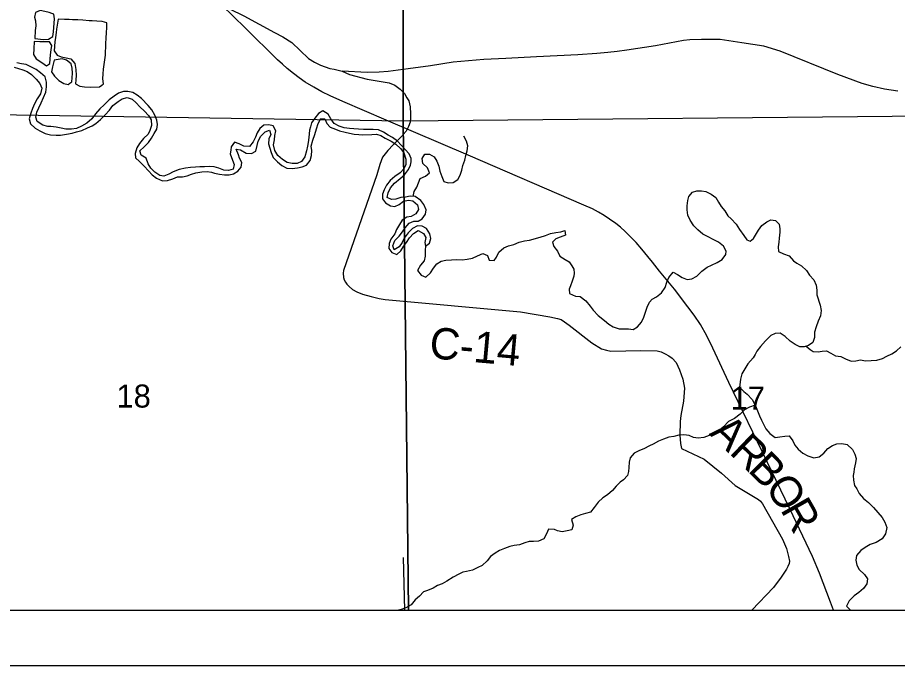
# Model space of a CAD drawing. Extents: x 0 to 34, y 0 to 22.
# Drawn here: x 6.566 to 8.162, y 14 to 15.175 of the extents above; entities that cross this region are included whole.
import ezdxf

# ---------------------------------------------------------------- set-up
doc = ezdxf.new("R2010")
doc.units = 0
for name, color, linetype in [('Default', 7, 'Continuous'), ('SH_Cut_Line', 7, 'Continuous'), ('SH_Data', 7, 'Continuous')]:
    doc.layers.add(name, color=color, linetype=linetype)

msp = doc.modelspace()

# ---------------------------------------------------------------- linework, layer by layer
at = {"layer": 'Default'}
msp.add_line((7.2687, 14.1), (7.2659, 14.1955), dxfattribs=at)
for points in [[(6.2892, 14.1), (8.9, 14.1), (8.9, 17.02), (8.2009, 17.0196), (7.211, 17.0191), (7.2045, 17.0191), (6.9328, 17.0189), (6.927, 17.0189), (6.6903, 17.0144), (6.3876, 17.0173), (6.3215, 17.0189), (6.2871, 17.0188), (6.2922, 16.0152), (6.2959, 15.2705), (6.2926, 14.8972), (6.2889, 14.4906), (6.2892, 14.18)], [(6.2943, 15.9991), (7.265, 16.0012), (7.2656, 14.9873), (6.2908, 15.0024), (6.2933, 15.4392)], [(8.2726, 16.0048), (8.2795, 14.9973), (7.2656, 14.9873), (7.265, 16.0012)], [(6.2854, 14.1), (7.2754, 14.1), (7.2656, 14.9873), (6.2908, 15.0024), (6.2858, 14.4391)], [(7.2754, 14.1), (8.2792, 14.1), (8.2795, 14.9973), (7.2656, 14.9873)]]:
    msp.add_lwpolyline(points, close=True, dxfattribs=at)
for points in [[(6.5394, 15.5399), (6.5899, 15.4855), (6.6708, 15.4021), (6.6928, 15.3789), (6.7527, 15.3164), (6.7777, 15.2904), (6.7991, 15.2728), (6.8123, 15.2654), (6.8735, 15.2322), (6.9245, 15.2039), (6.9768, 15.1783), (7.032, 15.1484), (7.0474, 15.1405), (7.0639, 15.1301), (7.0941, 15.1014), (7.1046, 15.0944), (7.1157, 15.0892), (7.1244, 15.0858), (7.1323, 15.083), (7.1403, 15.0815), (7.1549, 15.078)], [(8.046, 14.1), (8.0406, 14.1147), (8.021, 14.1674), (8.0082, 14.1978), (7.9667, 14.2843), (7.9256, 14.3692), (7.8563, 14.5132), (7.827, 14.5753), (7.8163, 14.5979), (7.8047, 14.6184), (7.7934, 14.6353), (7.782, 14.6504), (7.7575, 14.6826), (7.7308, 14.7151), (7.7176, 14.7314), (7.7092, 14.7421), (7.6986, 14.7552), (7.688, 14.767), (7.6773, 14.7784), (7.6682, 14.7875), (7.6597, 14.7951), (7.6512, 14.802), (7.6401, 14.8099), (7.6304, 14.8161), (7.6199, 14.8226), (7.6089, 14.8284), (7.5935, 14.8349), (7.3834, 14.9256), (7.235, 14.9895), (7.1561, 15.0234), (7.1332, 15.0336), (7.1183, 15.0408), (7.1038, 15.049), (7.0881, 15.0585), (7.077, 15.0663), (7.0666, 15.0738), (7.0552, 15.0829), (7.0465, 15.0906), (7.0376, 15.0989), (6.9791, 15.1568), (6.9366, 15.1982)], [(6.6281, 15.183), (6.6234, 15.1845), (6.6154, 15.1867), (6.6074, 15.1881), (6.5984, 15.1846), (6.5966, 15.1762), (6.5986, 15.1697), (6.5991, 15.1603), (6.5981, 15.1519), (6.5972, 15.1373)], [(6.5972, 15.1373), (6.6131, 15.1358), (6.6222, 15.1363), (6.6302, 15.141), (6.6312, 15.1493), (6.6322, 15.1573), (6.6325, 15.1653), (6.6331, 15.1733), (6.6322, 15.1816), (6.6281, 15.183)], [(6.6398, 15.1723), (6.6368, 15.1543), (6.6361, 15.1483), (6.6347, 15.1395), (6.6337, 15.1315), (6.6324, 15.1148), (6.6379, 15.1069), (6.6455, 15.1043), (6.6543, 15.1026), (6.6626, 15.1004), (6.67, 15.0921), (6.6717, 15.0812), (6.6722, 15.0705), (6.6719, 15.0625), (6.6713, 15.0549), (6.6793, 15.0509), (6.6877, 15.0495), (6.6976, 15.0492), (6.7146, 15.0495), (6.7193, 15.053)], [(6.7193, 15.053), (6.7218, 15.0549), (6.7209, 15.064), (6.7215, 15.0731), (6.7221, 15.0819), (6.7235, 15.0902), (6.7256, 15.1074), (6.7259, 15.1131), (6.7261, 15.1218), (6.7264, 15.1286), (6.7267, 15.1378), (6.7273, 15.1484), (6.7279, 15.1568), (6.7281, 15.1659), (6.7194, 15.168), (6.7099, 15.169), (6.7015, 15.1697), (6.6958, 15.1692), (6.6848, 15.1706), (6.6753, 15.1712), (6.6658, 15.1715), (6.6597, 15.1718), (6.6514, 15.1716), (6.6398, 15.1723)], [(6.5962, 15.1319), (6.5955, 15.1184), (6.5953, 15.1082), (6.6, 15.1006), (6.6103, 15.094), (6.6184, 15.0876), (6.6221, 15.0902)], [(6.6221, 15.0902), (6.6244, 15.0919), (6.625, 15.1002), (6.6261, 15.1079), (6.6271, 15.1166), (6.6281, 15.125), (6.6242, 15.1314), (6.6155, 15.1316), (6.6067, 15.1315), (6.5962, 15.1319)], [(8.1628, 15.0417), (8.1384, 15.0454), (8.1175, 15.0503), (8.0982, 15.0557), (8.054, 15.0719), (7.9493, 15.1147), (7.9197, 15.1233), (7.8796, 15.1294), (7.8403, 15.1355), (7.8068, 15.1359), (7.7853, 15.1353), (7.7741, 15.134), (7.7235, 15.124), (7.6714, 15.1161), (7.6538, 15.114), (7.6367, 15.1122), (7.6168, 15.1104), (7.5824, 15.108), (7.5074, 15.1041), (7.4516, 15.1011), (7.4118, 15.0996), (7.3564, 15.0946), (7.315, 15.088), (7.2749, 15.0821), (7.2383, 15.0777), (7.2221, 15.0763), (7.2004, 15.076), (7.1549, 15.078)], [(6.6327, 15.0982), (6.6294, 15.0859), (6.6277, 15.0771), (6.6331, 15.0692), (6.6408, 15.0613), (6.65, 15.0558), (6.658, 15.054), (6.6612, 15.0562)], [(6.6612, 15.0562), (6.6648, 15.0586), (6.6654, 15.0663), (6.6657, 15.0746), (6.6655, 15.0833), (6.6635, 15.0913), (6.6551, 15.098), (6.6471, 15.1006), (6.6327, 15.0982)], [(6.5599, 15.0856), (6.576, 15.0806), (6.5836, 15.0776), (6.5916, 15.0724), (6.5997, 15.0638)], [(6.6186, 15.0496), (6.6188, 15.0584), (6.6164, 15.0678), (6.6079, 15.0753), (6.5999, 15.0813), (6.5903, 15.0861), (6.5819, 15.0905), (6.5735, 15.0912), (6.5651, 15.0933)], [(7.1549, 15.078), (7.1685, 15.0719), (7.2001, 15.0636), (7.2404, 15.0568), (7.2507, 15.0529), (7.26, 15.0452), (7.2679, 15.0374), (7.2723, 15.0297), (7.2759, 15.0244), (7.2783, 15.0137), (7.2791, 15.0005), (7.2791, 14.9933), (7.2783, 14.9859), (7.275, 14.9776), (7.2709, 14.9696), (7.2656, 14.963)], [(6.5997, 15.0638), (6.6067, 15.0559), (6.6102, 15.0472), (6.6077, 15.0373), (6.6018, 15.0278), (6.597, 15.0189), (6.5933, 15.0105), (6.59, 15.0018), (6.5875, 14.9915), (6.5899, 14.9828), (6.598, 14.9745), (6.6064, 14.9701), (6.616, 14.9649), (6.6259, 14.9628), (6.6362, 14.9618), (6.6441, 14.9619), (6.6547, 14.9636), (6.665, 14.9656), (6.6733, 14.968), (6.6827, 14.9708), (6.6933, 14.9751), (6.7012, 14.979), (6.708, 14.9833), (6.7166, 14.9906), (6.7249, 14.9991), (6.7327, 15.0076), (6.7391, 15.016), (6.7484, 15.023), (6.756, 15.0277), (6.7651, 15.0301), (6.7738, 15.0272), (6.7811, 15.0208), (6.7881, 15.0137), (6.7965, 15.0054), (6.8035, 14.9979), (6.8085, 14.9897), (6.8091, 14.9794), (6.8058, 14.9703), (6.8028, 14.9638), (6.7946, 14.956), (6.7871, 14.9472), (6.7827, 14.9392), (6.7794, 14.9289), (6.7803, 14.9209), (6.7876, 14.9145), (6.7957, 14.9055), (6.8038, 14.8973), (6.8104, 14.8898), (6.8184, 14.8842), (6.8291, 14.8794), (6.8382, 14.8796), (6.8477, 14.8827), (6.856, 14.8863), (6.8655, 14.8864), (6.8738, 14.8884), (6.8814, 14.8912), (6.8897, 14.8936), (6.9003, 14.8956), (6.9098, 14.8961), (6.9178, 14.8947), (6.9235, 14.8933), (6.9326, 14.8912), (6.9414, 14.8898), (6.9497, 14.8899), (6.9577, 14.8919), (6.9656, 14.8966), (6.9719, 14.9042), (6.973, 14.9126), (6.969, 14.9205), (6.9667, 14.9266), (6.9624, 14.9364), (6.9703, 14.9357), (6.9807, 14.9294), (6.9906, 14.9288), (6.9981, 14.9331), (7.0006, 14.943), (7.0024, 14.9514), (7.0076, 14.9602), (7.0151, 14.9683), (7.0234, 14.9714), (7.0258, 14.9635), (7.0221, 14.9551), (7.0215, 14.9463), (7.0239, 14.9384), (7.0262, 14.9308), (7.0298, 14.9214), (7.0375, 14.9139), (7.0456, 14.9072), (7.0548, 14.902), (7.0643, 14.9014), (7.0741, 14.903), (7.0821, 14.9047), (7.09, 14.9074), (7.0971, 14.9159), (7.0992, 14.9254), (7.0999, 14.9342), (7.099, 14.9421), (7.1015, 14.9532), (7.1051, 14.9631), (7.1084, 14.9738), (7.1117, 14.9833)], [(7.1297, 14.9999), (7.1197, 15.0062), (7.1118, 15.0016), (7.1051, 14.9927), (7.0995, 14.9847), (7.0974, 14.977), (7.0955, 14.9713), (7.0942, 14.958), (7.0932, 14.9485), (7.0922, 14.942), (7.09, 14.9336), (7.0871, 14.923), (7.0812, 14.9145), (7.0732, 14.9106), (7.0641, 14.9109), (7.0554, 14.9126), (7.0466, 14.9178), (7.0385, 14.9249), (7.033, 14.9344), (7.0306, 14.9446), (7.032, 14.9533), (7.033, 14.9617), (7.0348, 14.9701), (7.0297, 14.9787), (7.0217, 14.9805), (7.013, 14.9804), (7.0055, 14.9742), (7.001, 14.9662), (6.9977, 14.9585), (6.9937, 14.9497), (6.9866, 14.9417), (6.9767, 14.9423), (6.9679, 14.9463), (6.9595, 14.9493), (6.9539, 14.9408), (6.9529, 14.9351), (6.9518, 14.9283), (6.9558, 14.9169), (6.9593, 14.9086), (6.9572, 14.9006), (6.9489, 14.8978), (6.9401, 14.8985), (6.9313, 14.9021), (6.923, 14.9043), (6.915, 14.905), (6.9051, 14.9048), (6.8967, 14.9043), (6.8888, 14.9038), (6.8797, 14.9033), (6.8706, 14.9024), (6.8592, 14.8996), (6.8483, 14.8953), (6.8404, 14.891), (6.8317, 14.8874), (6.8241, 14.8889), (6.8152, 14.8948), (6.8079, 14.9019), (6.8032, 14.9102), (6.7997, 14.9204), (6.7905, 14.926), (6.7881, 14.9339), (6.796, 14.9409), (6.8034, 14.9486), (6.809, 14.9566), (6.8138, 14.9651), (6.819, 14.9727), (6.8201, 14.9815), (6.8188, 14.9894), (6.8153, 14.9981), (6.8098, 15.0083), (6.8032, 15.0158), (6.7909, 15.0285), (6.7832, 15.0345), (6.7752, 15.0397), (6.766, 15.0415), (6.7581, 15.041), (6.749, 15.0382), (6.7411, 15.0331), (6.7324, 15.0262), (6.7235, 15.0173), (6.7156, 15.01), (6.7078, 15.0008), (6.701, 14.9919), (6.6917, 14.9838), (6.6819, 14.9784), (6.6728, 14.9744), (6.6641, 14.9728), (6.6538, 14.973), (6.6455, 14.9748), (6.6363, 14.9766), (6.6268, 14.978), (6.6211, 14.9779), (6.612, 14.98), (6.602, 14.9871), (6.5996, 14.9947), (6.601, 15.0038), (6.6047, 15.0115), (6.6091, 15.0206), (6.6135, 15.0302), (6.6176, 15.0401), (6.6186, 15.0496)], [(7.1117, 14.9833), (7.1161, 14.9925), (7.1237, 14.9915), (7.1269, 14.9832), (7.1334, 14.9768), (7.1426, 14.9728), (7.1502, 14.9702), (7.1601, 14.9677), (7.1681, 14.9659), (7.1769, 14.9641), (7.1849, 14.9635), (7.1925, 14.9628), (7.2088, 14.9631), (7.2172, 14.9639), (7.2252, 14.9614), (7.2328, 14.9566), (7.2436, 14.9514), (7.252, 14.9458), (7.2608, 14.9376), (7.2667, 14.9297), (7.2706, 14.9187), (7.2704, 14.9089), (7.2667, 14.9012), (7.26, 14.8939), (7.2506, 14.8873), (7.2423, 14.88), (7.2352, 14.8715), (7.2312, 14.8631), (7.2282, 14.8547), (7.228, 14.8467), (7.2334, 14.8392), (7.2426, 14.8336), (7.2506, 14.8326), (7.2585, 14.8365), (7.2664, 14.842), (7.2751, 14.844), (7.2831, 14.8429), (7.2916, 14.8355), (7.2932, 14.8271), (7.2888, 14.8195), (7.2801, 14.8144), (7.2721, 14.8132), (7.2635, 14.8081), (7.259, 14.8001), (7.2538, 14.7909), (7.2502, 14.7829), (7.2431, 14.7736), (7.2402, 14.7652), (7.2399, 14.7565), (7.245, 14.749), (7.2541, 14.7457), (7.2616, 14.7519), (7.2664, 14.7599), (7.2717, 14.7676), (7.2768, 14.776), (7.2843, 14.7837), (7.293, 14.7888), (7.3022, 14.7836), (7.3065, 14.7764), (7.3047, 14.7673), (7.3063, 14.7605)], [(7.3063, 14.7605), (7.3135, 14.7659), (7.316, 14.7743), (7.314, 14.783), (7.3077, 14.7928), (7.3001, 14.7972), (7.2913, 14.7975), (7.2827, 14.7928), (7.2744, 14.7847), (7.2677, 14.7751), (7.2637, 14.7675), (7.2581, 14.7594), (7.2491, 14.754), (7.2467, 14.7615), (7.2507, 14.7707), (7.2582, 14.7788), (7.2645, 14.7865), (7.2694, 14.7941), (7.2765, 14.8026), (7.2852, 14.8058), (7.2927, 14.8062), (7.3003, 14.8105), (7.3059, 14.8186), (7.3073, 14.8266), (7.3029, 14.836), (7.2975, 14.8435), (7.2872, 14.8506), (7.278, 14.8512), (7.2701, 14.8496), (7.2614, 14.8487), (7.2523, 14.8459), (7.2443, 14.8451), (7.2367, 14.8491), (7.2381, 14.8575), (7.2425, 14.8667), (7.2496, 14.8751), (7.2601, 14.8833), (7.268, 14.8902), (7.2754, 14.8998), (7.2787, 14.9078), (7.2802, 14.9136), (7.2801, 14.92), (7.2766, 14.9279), (7.2619, 14.9437), (7.2553, 14.9512), (7.2461, 14.9579), (7.2385, 14.9623), (7.23, 14.9672), (7.2209, 14.972), (7.2113, 14.9726), (7.2022, 14.9721), (7.1935, 14.9723), (7.1848, 14.973), (7.1764, 14.9736), (7.1684, 14.9743), (7.1585, 14.9753), (7.1494, 14.9785), (7.1406, 14.9834), (7.1344, 14.9916), (7.1297, 14.9999)], [(7.2656, 14.963), (7.2649, 14.9622), (7.2473, 14.9442), (7.2377, 14.9345), (7.2282, 14.9221), (7.2235, 14.9089), (7.2179, 14.8903), (7.1572, 14.7164), (7.1566, 14.7117), (7.1573, 14.7038), (7.1587, 14.6995), (7.1608, 14.6951), (7.1635, 14.6917), (7.1656, 14.6893), (7.1674, 14.6873), (7.1739, 14.6823), (7.1818, 14.6779), (7.1919, 14.6737), (7.2075, 14.6691), (7.2223, 14.6657), (7.2331, 14.6639), (7.4782, 14.6413), (7.5316, 14.6323), (7.5454, 14.6294), (7.5519, 14.6274), (7.5584, 14.6234), (7.5668, 14.6171), (7.6079, 14.5855), (7.6256, 14.5746), (7.6343, 14.5717), (7.6424, 14.5699), (7.6968, 14.5716), (7.7261, 14.5707), (7.7333, 14.5692), (7.741, 14.5655), (7.7475, 14.5619), (7.7533, 14.5573), (7.761, 14.5494), (7.7669, 14.5361), (7.7728, 14.5191), (7.7756, 14.5031), (7.7738, 14.4795), (7.7693, 14.4536), (7.7682, 14.4423), (7.7674, 14.4178), (7.7689, 14.4025), (7.7703, 14.3933), (7.8113, 14.3744), (7.8431, 14.3485), (7.8681, 14.3267), (7.9099, 14.3012), (7.9137, 14.2982), (7.9176, 14.2929), (7.9537, 14.229), (7.9607, 14.212), (7.9647, 14.1975), (7.9661, 14.189), (7.9656, 14.1846), (7.9634, 14.1793), (7.9608, 14.1746), (7.9515, 14.1601), (7.9372, 14.1413), (7.8982, 14.1)], [(7.284, 14.8508), (7.2855, 14.8597), (7.2903, 14.8677), (7.2933, 14.8754), (7.2966, 14.8834), (7.306, 14.8877), (7.3131, 14.8939), (7.31, 14.903), (7.3015, 14.9104), (7.3002, 14.9199), (7.3047, 14.9276), (7.3134, 14.9277), (7.3218, 14.9229), (7.3265, 14.9146), (7.3304, 14.9055), (7.3324, 14.8968), (7.336, 14.887), (7.3396, 14.8779), (7.3472, 14.8754), (7.3563, 14.8759), (7.3649, 14.8817), (7.369, 14.8897), (7.3719, 14.8985), (7.3741, 14.9073), (7.3774, 14.9165), (7.3795, 14.9252), (7.3817, 14.9336), (7.3831, 14.9427), (7.3803, 14.9514), (7.3756, 14.9601)], [(7.7805, 14.8265), (7.7807, 14.8341), (7.7817, 14.8436), (7.7839, 14.8508), (7.7906, 14.8585), (7.7982, 14.8613), (7.8069, 14.861), (7.8145, 14.8596), (7.8241, 14.8552), (7.8325, 14.8489), (7.8376, 14.8402), (7.8423, 14.8327), (7.8492, 14.8248), (7.8547, 14.8154), (7.8604, 14.8101), (7.8697, 14.8004), (7.8755, 14.791), (7.8837, 14.7801), (7.8891, 14.7722), (7.8948, 14.7696), (7.9012, 14.7746), (7.9049, 14.7804), (7.9101, 14.7896), (7.9164, 14.798), (7.9251, 14.805), (7.9326, 14.8085), (7.941, 14.8075), (7.9479, 14.8004), (7.9488, 14.792), (7.9489, 14.7859), (7.9479, 14.7753), (7.9473, 14.7681), (7.9459, 14.7593), (7.9464, 14.751), (7.9552, 14.7465), (7.9655, 14.7433), (7.9736, 14.7343), (7.9797, 14.7298), (7.9881, 14.725), (7.9974, 14.7167), (8.0028, 14.7081), (8.0105, 14.6995), (8.0145, 14.69), (8.0157, 14.6809), (8.0159, 14.6722), (8.0222, 14.6533), (8.0235, 14.6438), (8.0225, 14.6343), (8.0184, 14.6247), (8.0148, 14.6144), (8.0119, 14.6049), (8.0117, 14.595), (8.0088, 14.5859), (8.0009, 14.5804), (7.9929, 14.578), (7.9853, 14.5783), (7.9769, 14.582), (7.9673, 14.5883), (7.9585, 14.5965), (7.9493, 14.6025), (7.9405, 14.6024), (7.9322, 14.5984), (7.9229, 14.5888), (7.9135, 14.5788), (7.9072, 14.57), (7.9039, 14.5639), (7.9002, 14.5581), (7.8908, 14.547), (7.8853, 14.5381), (7.8801, 14.529), (7.8775, 14.5194), (7.8769, 14.5137), (7.8759, 14.505), (7.8836, 14.4967), (7.8897, 14.4919), (7.8986, 14.4825), (7.9048, 14.4708), (7.9084, 14.4617), (7.9119, 14.4531), (7.9158, 14.4451), (7.9205, 14.4353), (7.9237, 14.4293), (7.9306, 14.421), (7.9402, 14.4136), (7.9489, 14.4148), (7.9577, 14.4157), (7.9656, 14.4166), (7.9726, 14.4076), (7.9761, 14.3993), (7.9823, 14.3921), (7.9908, 14.385), (7.9999, 14.3802), (8.0106, 14.3766), (8.0201, 14.3782), (8.0287, 14.3852), (8.0358, 14.3937), (8.0445, 14.3991), (8.0524, 14.4023), (8.0615, 14.4024), (8.0707, 14.4006), (8.0807, 14.3916)], [(7.3063, 14.7605), (7.3053, 14.7532), (7.3054, 14.7426), (7.3037, 14.7342), (7.2973, 14.7262), (7.2918, 14.7166), (7.2983, 14.708), (7.3067, 14.7047), (7.315, 14.7124), (7.3209, 14.7208), (7.3269, 14.7285), (7.3348, 14.7332), (7.3431, 14.7352), (7.353, 14.7361), (7.3632, 14.7366), (7.3727, 14.736), (7.3815, 14.7369), (7.3913, 14.7389), (7.4007, 14.7432), (7.4098, 14.7475), (7.4186, 14.7438), (7.4217, 14.7355), (7.4305, 14.7345), (7.435, 14.7407), (7.4394, 14.7495), (7.448, 14.7576), (7.4567, 14.7611), (7.4665, 14.7639), (7.4763, 14.7678), (7.4854, 14.7702), (7.4945, 14.7715), (7.5142, 14.7767), (7.524, 14.7803), (7.5331, 14.7834), (7.5425, 14.7855), (7.5513, 14.7867), (7.5588, 14.7888), (7.5601, 14.7808), (7.5506, 14.7769), (7.5423, 14.7737), (7.5367, 14.7679), (7.5391, 14.76), (7.5453, 14.7517), (7.5496, 14.7427), (7.5592, 14.7367), (7.5669, 14.7323), (7.5715, 14.7247), (7.575, 14.7187), (7.5759, 14.7119), (7.5752, 14.7062), (7.5723, 14.697), (7.5694, 14.6886), (7.5668, 14.6825), (7.5673, 14.6749), (7.578, 14.6698), (7.5868, 14.6691), (7.5971, 14.6613), (7.6049, 14.6519), (7.6103, 14.6444), (7.6195, 14.635), (7.6307, 14.6257), (7.6384, 14.619), (7.6468, 14.6145), (7.6571, 14.6109), (7.6655, 14.6106), (7.6742, 14.6104), (7.6826, 14.6097), (7.6909, 14.614), (7.6976, 14.6225), (7.7024, 14.6316), (7.7082, 14.65), (7.7122, 14.6588), (7.7171, 14.6645), (7.7254, 14.6688), (7.734, 14.6762), (7.7411, 14.6858), (7.744, 14.6953), (7.7473, 14.7041), (7.7555, 14.7137), (7.7632, 14.7092), (7.7716, 14.704), (7.7808, 14.7004), (7.7895, 14.7013), (7.7985, 14.7063), (7.8075, 14.7152), (7.8173, 14.7225), (7.8248, 14.7261), (7.835, 14.7308), (7.8444, 14.7362), (7.8511, 14.7458), (7.8514, 14.7515), (7.8467, 14.7609), (7.8375, 14.768), (7.8279, 14.7728), (7.8191, 14.7773), (7.8092, 14.7824), (7.8, 14.7903), (7.793, 14.7978), (7.7864, 14.8076), (7.7821, 14.817), (7.7805, 14.8265)], [(7.9964, 14.5791), (8.0036, 14.5729), (8.0094, 14.5695), (8.0181, 14.5689), (8.0257, 14.5702), (8.0337, 14.5706), (8.0413, 14.5666), (8.0497, 14.5614), (8.0592, 14.5604), (8.068, 14.5563), (8.078, 14.5523), (8.0867, 14.5524), (8.095, 14.5544), (8.1042, 14.5527), (8.1144, 14.5532), (8.125, 14.5541), (8.1353, 14.5569), (8.1428, 14.5612), (8.1518, 14.5651), (8.1605, 14.5705), (8.1684, 14.5783)], [(7.9042, 14.472), (7.8938, 14.4688), (7.8848, 14.4637), (7.8766, 14.4556), (7.8664, 14.4482), (7.8559, 14.4424), (7.8465, 14.4331), (7.8383, 14.4254), (7.8296, 14.4204), (7.8209, 14.4172), (7.8111, 14.4133), (7.8005, 14.412), (7.7925, 14.4134), (7.7841, 14.4174), (7.7749, 14.4184), (7.7658, 14.4179), (7.7568, 14.4155), (7.7477, 14.4139), (7.7378, 14.4103), (7.7288, 14.4068), (7.719, 14.4013), (7.7126, 14.3986), (7.7024, 14.3931), (7.6941, 14.39), (7.6847, 14.3849), (7.6772, 14.3768), (7.6754, 14.3688), (7.6748, 14.3593), (7.6741, 14.3517), (7.6723, 14.3448), (7.6652, 14.3364), (7.6592, 14.3325), (7.6517, 14.3252), (7.6454, 14.3175), (7.6364, 14.3097), (7.6277, 14.3039), (7.6195, 14.2962), (7.612, 14.2862), (7.6053, 14.2778), (7.5962, 14.2757), (7.5879, 14.273), (7.5785, 14.2694), (7.5709, 14.2648), (7.5741, 14.2545), (7.5716, 14.2458), (7.5629, 14.2441), (7.5538, 14.2421), (7.5458, 14.2439), (7.5401, 14.2465), (7.5294, 14.2471), (7.5254, 14.2387), (7.5209, 14.2299), (7.5108, 14.2255), (7.502, 14.225), (7.4944, 14.2249), (7.4861, 14.2221), (7.4767, 14.2186), (7.4672, 14.2177), (7.4589, 14.2157), (7.4494, 14.2121), (7.4404, 14.2082), (7.4324, 14.2039), (7.4242, 14.1977), (7.4178, 14.19), (7.4088, 14.1815), (7.4009, 14.1776), (7.3911, 14.1729), (7.3805, 14.1701), (7.3741, 14.1689), (7.3665, 14.1657), (7.356, 14.1603), (7.3447, 14.1529), (7.3364, 14.1478), (7.3277, 14.1447), (7.3198, 14.14), (7.31, 14.1357), (7.3024, 14.1337), (7.2953, 14.1256), (7.2875, 14.1187), (7.28, 14.1102), (7.2706, 14.1047), (7.2619, 14.1016), (7.257, 14.1)], [(8.0807, 14.3916), (8.0846, 14.3833), (8.0874, 14.3754), (8.0863, 14.3674), (8.0838, 14.3567), (8.0828, 14.3507), (8.0821, 14.3446), (8.0822, 14.3358), (8.0843, 14.3267), (8.0882, 14.3203), (8.0928, 14.312), (8.1006, 14.303), (8.1098, 14.2956), (8.1186, 14.2866), (8.1264, 14.2772), (8.1345, 14.2686), (8.1395, 14.2599), (8.1427, 14.2505), (8.1402, 14.239), (8.1346, 14.2298), (8.1234, 14.2232), (8.1124, 14.2193), (8.1037, 14.2142), (8.0955, 14.2084), (8.088, 14.1995), (8.0866, 14.1908), (8.0886, 14.1817), (8.0929, 14.1738), (8.1022, 14.1652), (8.1076, 14.1573), (8.1066, 14.1481), (8.1003, 14.1393), (8.0924, 14.1324), (8.0834, 14.1262), (8.0744, 14.1173), (8.0699, 14.1077), (8.0765, 14.1006), (8.0804, 14.1)]]:
    msp.add_lwpolyline(points, dxfattribs=at)
at = {"layer": 'SH_Cut_Line'}
msp.add_lwpolyline([(2.1, 17.0156), (2.1, 14.1), (8.9, 14.1), (8.9, 17.02)], dxfattribs=at)
at = {"layer": 'SH_Data'}
for p, q in [((2.1, 14.1), (8.9, 14.1)), ((2, 14), (9, 14))]:
    msp.add_line(p, q, dxfattribs=at)

# ---------------------------------------------------------------- texts
at = {"layer": 'Default'}
for s, height, rotation, p in [('C-14', 0.05682, 354.8676, (7.3117, 14.5577)), ('18', 0.04186, 0, (6.7456, 14.4678)), ('17', 0.04186, 0, (7.8597, 14.4641)), ('A', 0.0568, 316.3344, (7.8193, 14.4197)), ('R', 0.0568, 316.3331, (7.8555, 14.3852)), ('B', 0.0568, 314.8731, (7.889, 14.3532)), ('O', 0.0568, 305.887, (7.9204, 14.322)), ('R', 0.0568, 299.649, (7.9488, 14.2828))]:
    msp.add_text(s, height=height, rotation=rotation, dxfattribs=at).set_placement(p)

doc.saveas('drawing.dxf')
